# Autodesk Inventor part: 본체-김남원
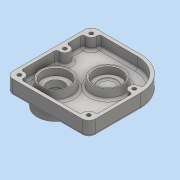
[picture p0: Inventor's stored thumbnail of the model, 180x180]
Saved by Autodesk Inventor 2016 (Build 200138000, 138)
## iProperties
Created: 2015-11
Part Number: 본체-김남원
Material: 일반
Document SubType Name: Modeling
Designer: KET-DEVEL
Density: 1 g/cm^3
Appearance: 기본값
Mass: 91.2711 g
Surface Area: 389.784 cm^2
Volume: 91.2711 cm^3
Author: KET-DEVEL
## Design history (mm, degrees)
sketch "스케치1"
  geometry: L1 (-42, 51.5)-(10, 51.5); L2 (50, 11.5)-(50, -43.5); L3 (42, -51.5)-(-42, -51.5); L4 (-50, -43.5)-(-50, 43.5); L5 (-50, 51.5)-(50, -51.5); A1 r 8 centre (-42, 43.5) between (-42, 51.5) and (-50, 43.5); A2 r 8 centre (-42, -43.5) between (-50, -43.5) and (-42, -51.5); A3 r 8 centre (42, -43.5) between (42, -51.5) and (50, -43.5); A4 r 40 centre (10, 11.5) between (50, 11.5) and (10, 51.5); 2 further points
  constraints: 10 end point, 8 point on circle, 8 tangent, 4 centre point, 4 point on line, 2 equal radius, 2 parallel, 1 coincident, 1 horizontal, 1 midpoint, 1 perpendicular
  dimensions: "d1" = 103 distance between parallel lines of L3 L1; "d2" = 100 distance between parallel lines of L2 L4; "d3" = 8 radius of A1; "d4" = 40 radius of A4
extrude "돌출1" new body sketch "스케치1" distance "d5" = 4; taper "d6" = 0 deg
sketch "스케치2"
  geometry: L1 (10, 51.5)-(-42, 51.5) reference; L2 (-50, 43.5)-(-50, -43.5) reference; L3 (-42, -51.5)-(42, -51.5) reference; L4 (50, -43.5)-(50, 11.5) reference; L5 (-42, 43.5)-(42, 43.5); L6 (42, 43.5)-(42, -43.5); L7 (42, -43.5)-(-42, -43.5); L8 (-42, -43.5)-(-42, 43.5); L9 (-42, 11.5)-(42, 11.5); L10 (-33.056, 47.5)-(10, 47.5); L11 (46, 2.556)-(46, -34.556); L12 (33.056, -47.5)-(-33.056, -47.5); L13 (-46, -34.556)-(-46, 2.556); L14 (-46, 20.444)-(-46, 34.556); A1 r 8 centre (-42, 43.5) between (-42, 51.5) and (-50, 43.5) reference; A2 r 8 centre (-42, -43.5) between (-50, -43.5) and (-42, -51.5) reference; A3 r 8 centre (42, -43.5) between (42, -51.5) and (50, -43.5) reference; A4 r 40 centre (10, 11.5) between (50, 11.5) and (10, 51.5) reference; A5 r 6 centre (-42, 11.5) between (-42.667, 5.537) and (-42.667, 17.463); A6 r 6 centre (-42, -43.5) between (-36.037, -44.167) and (-42.667, -37.537); A7 r 6 centre (42, -43.5) between (42.667, -37.537) and (36.037, -44.167); A8 r 6 centre (42, 11.5) between (41.833, 17.498) and (42.667, 5.537); A9 r 6 centre (-42, 43.5) between (-42.667, 37.537) and (-36.037, 44.167); A10 r 36 centre (10, 11.5) between (44.636, 21.314) and (10, 47.5); A11 r 3 centre (-33.056, 44.5) between (-33.056, 47.5) and (-36.037, 44.167); A12 r 3 centre (-43, 34.556) between (-42.667, 37.537) and (-46, 34.556); A13 r 3 centre (-43, 20.444) between (-46, 20.444) and (-42.667, 17.463); A14 r 3 centre (-43, 2.556) between (-42.667, 5.537) and (-46, 2.556); A15 r 3 centre (-43, -34.556) between (-46, -34.556) and (-42.667, -37.537); A16 r 3 centre (-33.056, -44.5) between (-36.037, -44.167) and (-33.056, -47.5); A17 r 3 centre (33.056, -44.5) between (33.056, -47.5) and (36.037, -44.167); A18 r 3 centre (43, -34.556) between (42.667, -37.537) and (46, -34.556); A19 r 3 centre (43, 2.556) between (46, 2.556) and (42.667, 5.537); A20 r 3 centre (41.75, 20.497) between (41.833, 17.498) and (44.636, 21.314); 10 further points
  constraints: 41 point on circle, 20 end point, 20 tangent, 16 centre point, 13 equal radius, 11 point on line, 5 coincident, 2 parallel, 2 perpendicular, 1 horizontal
  dimensions: "d7" = 12 diameter of A9; "d8" = 84 distance between parallel lines of L6 L8; "d9" = 87 distance between parallel lines of L5 L7; "d10" = 8 distance between parallel lines of L3 L7; "d11" = 8 distance between parallel lines of L2 L8; "d12" = 55 distance between parallel lines of L7 L9; "d13" = 4 distance between parallel lines of L1 L10; "d14" = 3 radius of A11
extrude "돌출2" join sketch "스케치2" distance "d15" = 14; taper "d16" = 0 deg
sketch "스케치3"
  geometry: A1 r 6 centre (42, 43.5) between (36.037, 44.167) and (42.667, 37.537) reference; A2 r 6 centre (42, 11.5) between (42.667, 17.463) and (42.667, 5.537) reference; A3 r 6 centre (42, -43.5) between (42.667, -37.537) and (36.037, -44.167) reference; A4 r 6 centre (-42, -43.5) between (-36.037, -44.167) and (-42.667, -37.537) reference; A5 r 6 centre (-42, 11.5) between (-42.667, 5.537) and (-41.833, 17.498) reference; 1 further point
sketch "스케치4"
  geometry: L1 (-42, -51.5)-(42, -51.5) reference; L2 (-50, 43.5)-(-50, -43.5) reference; C1 r 20 at (-20, -21.5); 1 further point
  constraints: 1 centre point
  dimensions: "d17" = 30 distance from line of L1 C1.centre; "d18" = 30 distance from line of L2 C1.centre; "d19" = 40 diameter of C1
extrude "돌출3" join sketch "스케치4" distance "d20" = 11; taper "d21" = -10 deg
sketch "스케치5"
  geometry: C1 r 20 at (20, -21.5) reference; C2 r 25 at (20, -21.5); 1 further point
  constraints: 1 centre point, 1 coincident
  dimensions: "d22" = 50 diameter of C2
extrude "돌출4" join sketch "스케치5" distance "d23" = 15; taper "d24" = -10 deg
sketch "스케치6" dims "d25" = 36
  geometry: C1 r 14 at (0, 0); C2 r 12 at (0, 0); 3 further points
  constraints: 2 centre point, 2 coincident, 1 horizontal alignment, 2 other
  dimensions: "d26" = 28 diameter of C1; "d27" = 24 diameter of C2
extrude "돌출5" cut sketch "스케치6" distance "d28" = 11; taper "d29" = 0 deg
extrude "돌출6" cut sketch "스케치6" distance "d30" = 13; taper "d31" = 0 deg
sketch "스케치7"
  geometry: C1 r 16 at (0, 0); C2 r 10 at (0, 0); 1 further point
  constraints: 2 centre point, 1 coincident
  dimensions: "d32" = 32 diameter of C1; "d33" = 20 diameter of C2
extrude "돌출7" cut sketch "스케치7" distance "d34" = 9; taper "d35" = 0 deg
extrude "돌출8" cut sketch "스케치7" stored distance "d36" = 9; taper "d37" = 0 deg
sketch "스케치8"
  geometry: L1 (-42, -51.5)-(42, -51.5) reference; L2 (-50, 43.5)-(-50, -43.5) reference; C1 r 20 at (10, 11.5); 1 further point
  constraints: 1 centre point
  dimensions: "d38" = 63 distance from line of L1 C1.centre; "d39" = 60 distance from line of L2 C1.centre; "d40" = 40 diameter of C1
extrude "돌출9" join sketch "스케치8" distance "d41" = 11; taper "d42" = -10 deg
sketch "스케치9"
  geometry: C1 r 16 at (0, 0); C2 r 11 at (0, 0); 1 further point
  constraints: 2 centre point, 1 coincident
  dimensions: "d43" = 32 diameter of C1; "d44" = 22 diameter of C2
extrude "돌출10" cut sketch "스케치9" distance "d45" = 11; taper "d46" = 0 deg
extrude "돌출11" cut sketch "스케치9" distance "d47" = 9; taper "d48" = 0 deg
hole "구멍1" sketch "스케치3" diameter "d49" = 4.5; stored, may be unused: countersink angle "d53" = 90 deg, drill point angle "d55" = 118 deg; dims "d50" = 6, "d51" = 8, "d52" = 4.4, "d54" = 8
hole "구멍2" sketch "스케치6" diameter "d56" = 2.459; stored, may be unused: countersink angle "d60" = 90 deg, drill point angle "d62" = 118 deg; dims "d57" = 8, "d58" = 8, "d59" = 4.4, "d61" = 10
sketch "스케치10"
  geometry: L1 (-14.887, 45.225)-(34.887, 45.225); L2 (34.887, 45.225)-(34.887, 17.775); L3 (34.887, 17.775)-(-14.887, 17.775); L4 (-14.887, 17.775)-(-14.887, 45.225); L5 (50, -43.5)-(50, 43.5) reference; L6 (42, 51.5)-(-10, 51.5) reference; 3 further points
  constraints: 2 midpoint, 2 other
  dimensions: "d66" = 40 distance from line of L5 point (10, 45.225); "d67" = 20 distance from line of L6 point (34.887, 31.5)
extrude "돌출12" join sketch "스케치10" distance "d68" = 0.5; taper "d69" = 0 deg
chamfer "모따기1" distance "d70" = 1; stored, may be unused: second distance "d71" = 2, angle "d72" = 45 deg
fillet "모깎기1" dims "d73" = 0.3
fillet "모깎기2" dims "d74" = 3
fillet "모깎기3" dims "d75" = 2
node "솔리드1"
pattern_circular "원형 패턴1" dims angle "d64" = 360 deg
node "투영된 루프1"
